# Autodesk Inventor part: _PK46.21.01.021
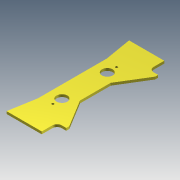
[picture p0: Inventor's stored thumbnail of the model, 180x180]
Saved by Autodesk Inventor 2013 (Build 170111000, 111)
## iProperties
Created: 2005-04
Part Number: _PK46.21.01.021
Material: Steel, Mild
Document SubType Name: Modeling
Designer: salex
Manufacturer: Standard
Standards Organization: Custom
Density: 7.86 g/cm^3
Author: salex
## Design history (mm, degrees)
sketch "Эскиз1"
  geometry: L1 (0, 0)-(378.386, 0); L2 (0, -225)-(0, 225); L3 (0, 225)-(-30, 400); L4 (-30, 400)-(200, 400); L5 (200, 400)-(200, 280); L6 (200, 280)-(150, 100); L7 (150, 100)-(150, -100); L8 (200, -280)-(150, -100); L9 (0, -225)-(-30, -400); L10 (-30, -400)-(200, -400); L11 (200, -400)-(200, -280); C1 r 35 at (80, 148); C2 r 8 at (80, 208); C3 r 35 at (80, -148); C4 r 8 at (80, -208)
  constraints: 22 end point, 7 symmetric about line, 4 centre point, 3 perpendicular, 1 horizontal, 1 parallel, 3 other
  dimensions: "d0" = 0 distance from line of L1.start L2; "d1" = 800 diameter of L4 L1; "d2" = 450 diameter of L2.end L1; "d3" = 200 diameter of L6.end L1; "d4" = 120 distance of L4.end L5.end; "d5" = 120 distance from line of L5 C1.centre; "d6" = 60 distance of C2.centre C1.centre; "d7" = 296 diameter of C1.centre L1; "d8" = 0 horizontal distance of C1.centre C2.centre; "d9" = 70 diameter of C1; "d10" = 16 diameter of C2; "d11" = 230 distance of L3.end L4.end; "d12" = 50 distance between parallel lines of L5 L7; "d16" = 150 distance between parallel lines of L7 L2
extrude "Выдавливание1" new body sketch "Эскиз1" distance "d14" = 16; taper "d15" = 0 deg
sketch "Эскиз2"
  geometry: L1 (150, 100)-(150, -100) reference; L2 (200, 280)-(150, 100) reference; L3 (200, 400)-(200, 280) reference; L4 (-30, 400)-(200, 400) reference; L5 (150, 100)-(260, 280); L6 (260, 280)-(260, 300); L7 (260, 300)-(230, 300); A1 r 30 centre (230, 330) between (200, 330) and (230, 300)
  constraints: 6 end point, 2 perpendicular, 2 point on circle, 2 tangent, 1 centre point, 1 point on line
  dimensions: "d17" = 100 distance between parallel lines of L4 L7; "d18" = 30 radius of A1; "d19" = 120 distance from line of L5.end L4; "d20" = 110 distance between parallel lines of L6 L1
extrude "Выдавливание2" join sketch "Эскиз2" stored distance "d21" = 10; taper "d22" = 0 deg
mirror "ЗеркОтобр1"
sketch "Эскиз3"
  geometry: L1 (150, 100)-(260, 280) reference; L2 (260, 280)-(260, 300) reference; L3 (260, 300)-(230, 300) reference; L4 (170.089, 257.031)-(250, 285) reference; L5 (250, 285)-(250, 300) reference; L6 (150, 100)-(163.158, 235.965) reference; A1 r 30 centre (180, 228.716) between (170.089, 257.031) and (150, 228.716) reference
extrude "Выдавливание3" cut sketch "Эскиз3" stored distance "d24" = 10; taper "d25" = 0 deg
body "Solid1"
node "ЗаимстЛин1"
node "ЗаимстЛин2"
node "ЗаимстЛин3"
node "ЗаимстЛин4"
